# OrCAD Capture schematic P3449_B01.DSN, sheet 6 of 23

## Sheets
6 0017_DisplayPort: size Custom
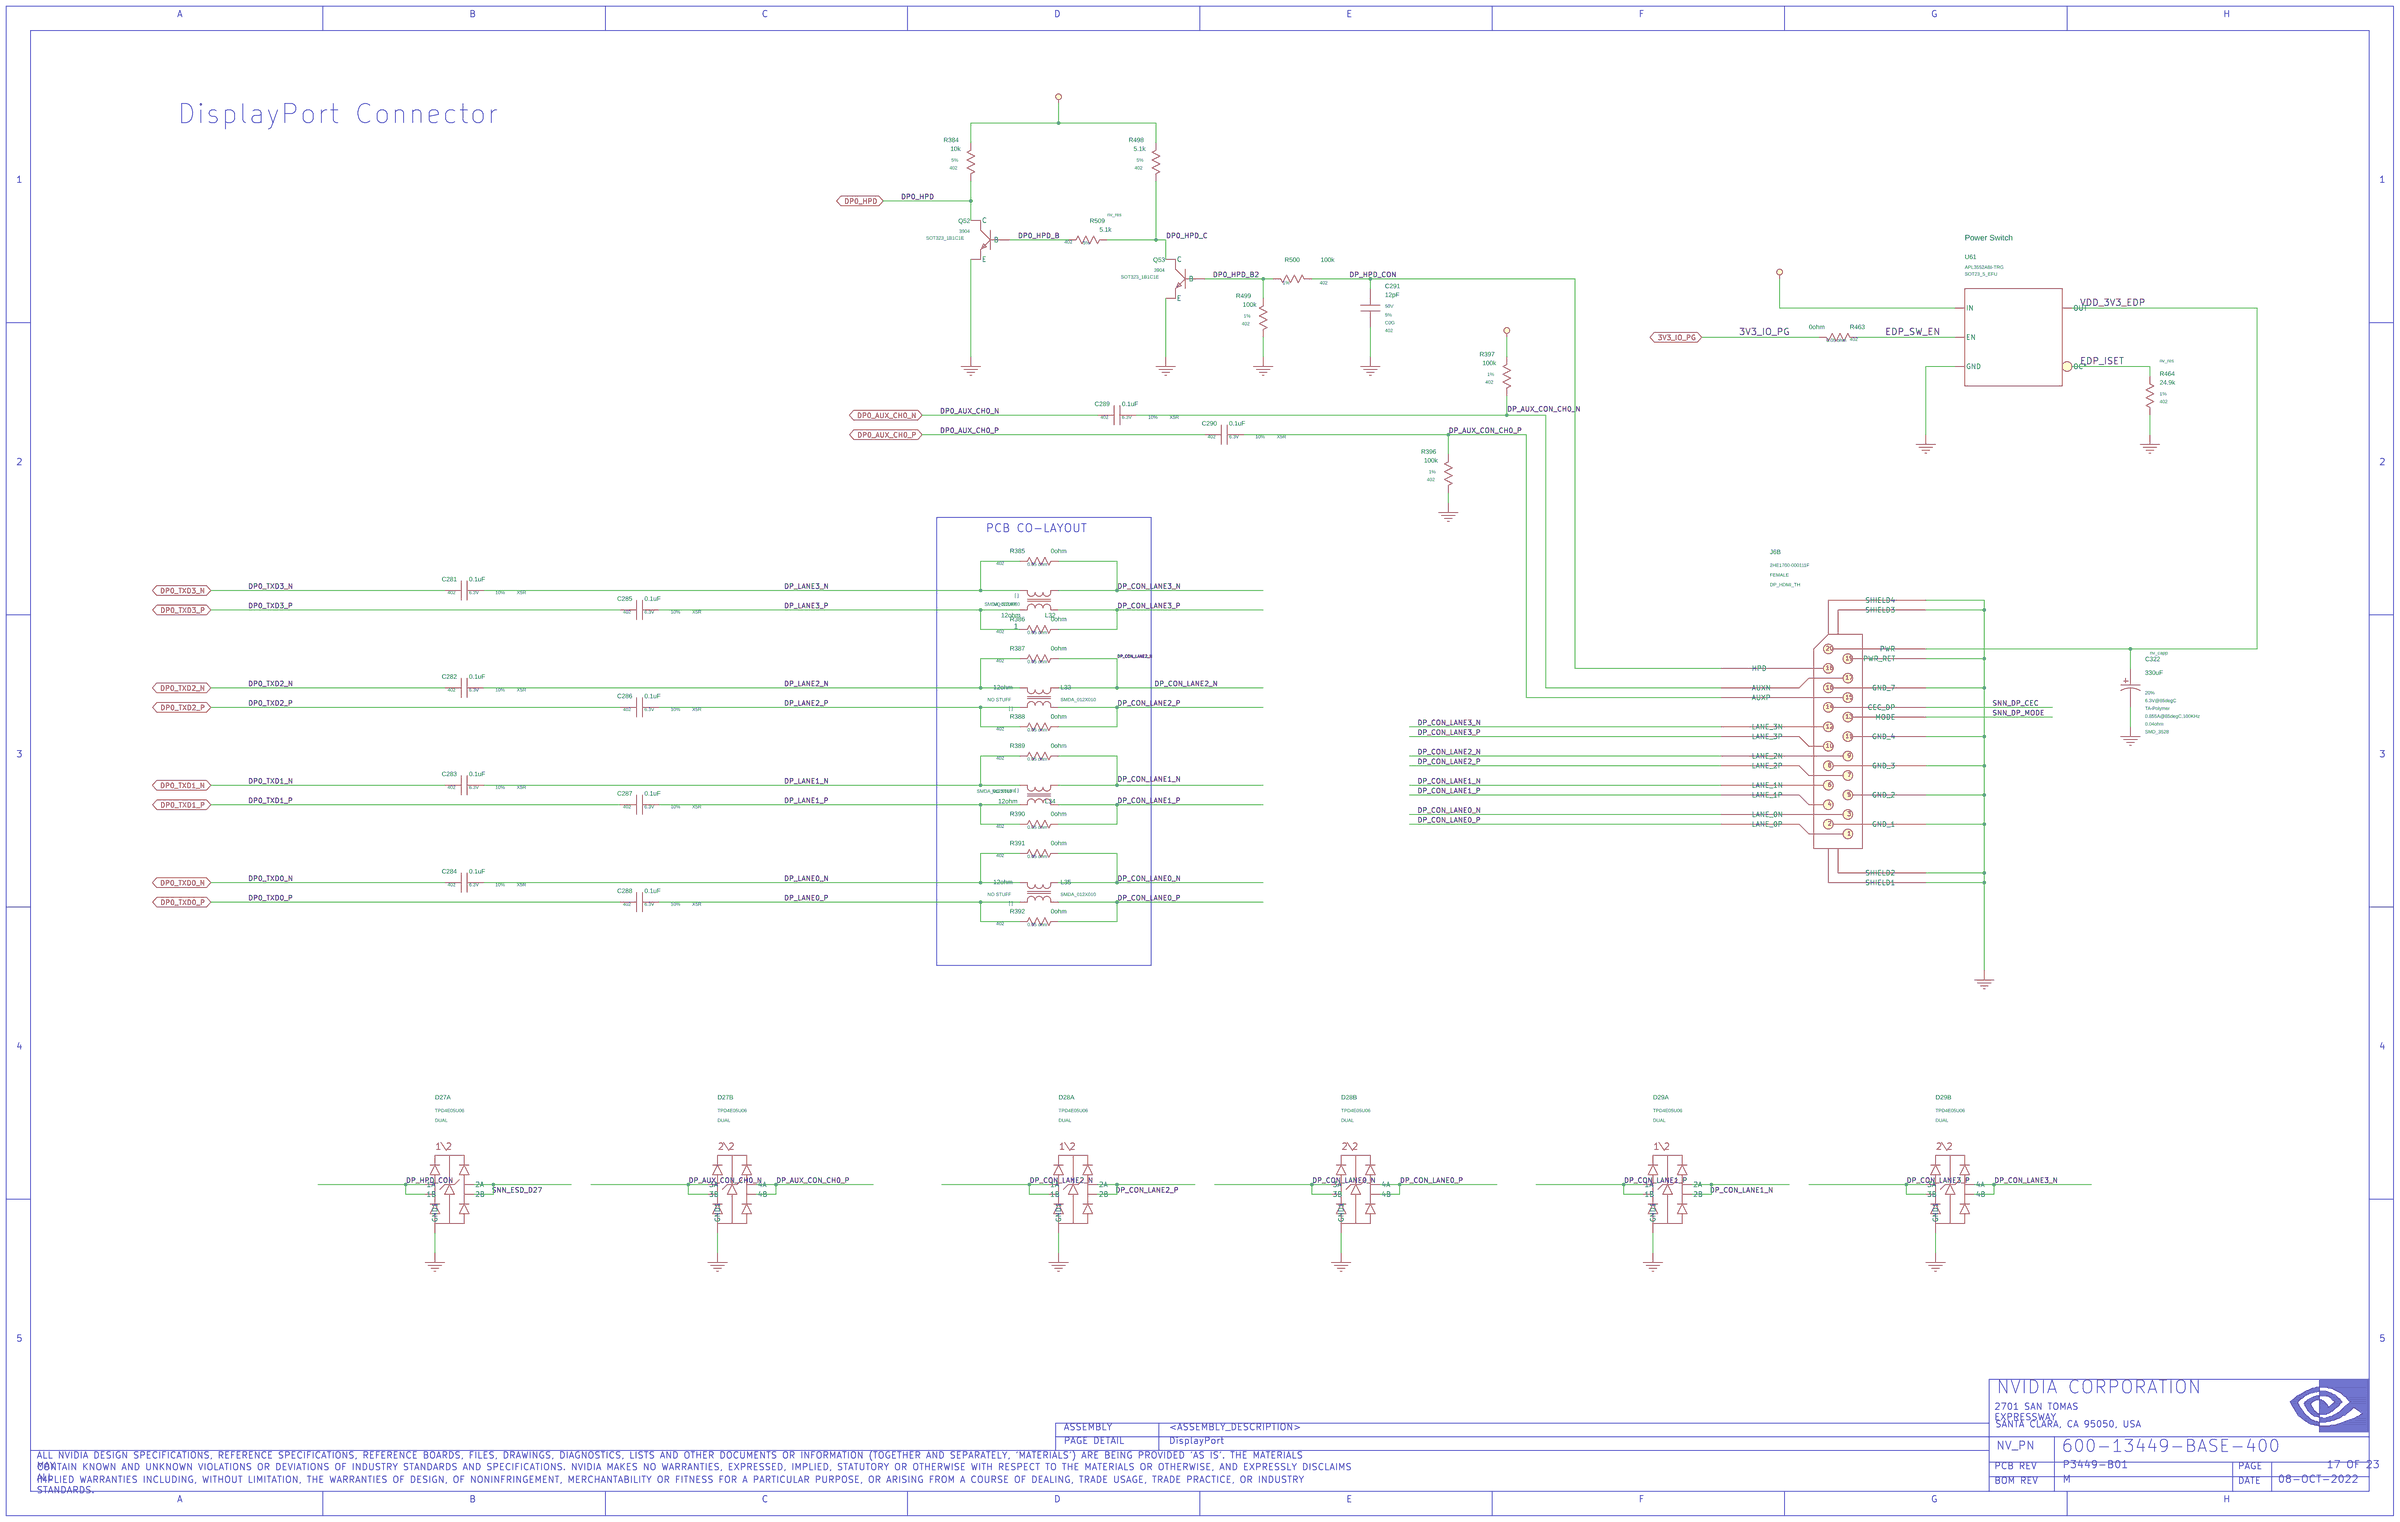
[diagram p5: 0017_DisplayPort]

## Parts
C281  0.1uF  [402]
C282  0.1uF  [402]
C283  0.1uF  [402]
C284  0.1uF  [402]
C285  0.1uF  [402]
C286  0.1uF  [402]
C287  0.1uF  [402]
C288  0.1uF  [402]
C289  0.1uF  [402]
C290  0.1uF  [402]
C291  12pF  [402]
C322  330uF  [CAP_SMD_3528]
D27  D_ESD_DIFFPAIR  [TSLP10_P050_025X010]  (sections A,B)
D28  D_ESD_DIFFPAIR  [TSLP10_P050_025X010]  (sections A,B)
D29  D_ESD_DIFFPAIR  [TSLP10_P050_025X010]  (sections A,B)
J6  CON_HDMI_DISPLAYPORT  [CON_HDMI_019_DP_020_TH_RA_F_181X180_B]  (sections A,B)
L32  12ohm  [IND_NONRKO_SMD_012X010]
L33  12ohm  [IND_NONRKO_SMD_012X010]
L34  12ohm  [IND_NONRKO_SMD_012X010]
L35  12ohm  [IND_NONRKO_SMD_012X010]
Q52  Q_NPN  [SOT323_D]
Q53  Q_NPN  [SOT323_D]
R384  10k  [402]
R385  0ohm  [402]
R386  0ohm  [402]
R387  0ohm  [402]
R388  0ohm  [402]
R389  0ohm  [402]
R390  0ohm  [402]
R391  0ohm  [402]
R392  0ohm  [402]
R396  100k  [402]
R397  100k  [402]
R463  0ohm  [402]
R464  24.9k  [402]
R498  5.1k  [402]
R499  100k  [402]
R500  100k  [402]
R509  5.1k  [402]
U61  U_PWR_SW_UL  [SOT23_5]

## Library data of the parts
C281 = C: ASSEMBLY: EDP; CDS_LIB: discrete; CDS_PART_NAME: C_0402-0.1UF,X5R,10%,6.3V,039-0007-000; CDS_PHYS_PART_NAME: C_0402-0.1UF,X5R,10%,6.3V,039-0007-000-0.1UF,039-0007-000; CDS_SEC: 1; DEVICE_TYPENAME: C_0402-01UFX5R1063V039-0007-000-01UF039-0007-000; DRAWING: @P3449_B01_LIB.P3449_B01(SCH_1):PAGE17; MAT: X5R; MAX_VOLTAGE: 6.3V; NO_XNET: 1; NV_PN: 039-0007-000; PATH: I22; PHYS_PAGE: 17; ROT: 0; SEC: 1; SIGNAL_MODEL: nv_cap; TOL: 10%; VER: 2; XY: (-9800,4600)
C282 = C: ASSEMBLY: EDP; CDS_LIB: discrete; CDS_PART_NAME: C_0402-0.1UF,X5R,10%,6.3V,039-0007-000; CDS_PHYS_PART_NAME: C_0402-0.1UF,X5R,10%,6.3V,039-0007-000-0.1UF,039-0007-000; CDS_SEC: 1; DEVICE_TYPENAME: C_0402-01UFX5R1063V039-0007-000-01UF039-0007-000; DRAWING: @P3449_B01_LIB.P3449_B01(SCH_1):PAGE17; MAT: X5R; MAX_VOLTAGE: 6.3V; NO_XNET: 1; NV_PN: 039-0007-000; PATH: I28; PHYS_PAGE: 17; ROT: 0; SEC: 1; SIGNAL_MODEL: nv_cap; TOL: 10%; VER: 2; XY: (-9800,4100)
C283 = C: ASSEMBLY: EDP; CDS_LIB: discrete; CDS_PART_NAME: C_0402-0.1UF,X5R,10%,6.3V,039-0007-000; CDS_PHYS_PART_NAME: C_0402-0.1UF,X5R,10%,6.3V,039-0007-000-0.1UF,039-0007-000; CDS_SEC: 1; DEVICE_TYPENAME: C_0402-01UFX5R1063V039-0007-000-01UF039-0007-000; DRAWING: @P3449_B01_LIB.P3449_B01(SCH_1):PAGE17; MAT: X5R; MAX_VOLTAGE: 6.3V; NO_XNET: 1; NV_PN: 039-0007-000; PATH: I29; PHYS_PAGE: 17; ROT: 0; SEC: 1; SIGNAL_MODEL: nv_cap; TOL: 10%; VER: 2; XY: (-9800,3600)
C284 = C: ASSEMBLY: EDP; CDS_LIB: discrete; CDS_PART_NAME: C_0402-0.1UF,X5R,10%,6.3V,039-0007-000; CDS_PHYS_PART_NAME: C_0402-0.1UF,X5R,10%,6.3V,039-0007-000-0.1UF,039-0007-000; CDS_SEC: 1; DEVICE_TYPENAME: C_0402-01UFX5R1063V039-0007-000-01UF039-0007-000; DRAWING: @P3449_B01_LIB.P3449_B01(SCH_1):PAGE17; MAT: X5R; MAX_VOLTAGE: 6.3V; NO_XNET: 1; NV_PN: 039-0007-000; PATH: I27; PHYS_PAGE: 17; ROT: 0; SEC: 1; SIGNAL_MODEL: nv_cap; TOL: 10%; VER: 2; XY: (-9800,3100)
C285 = C: ASSEMBLY: EDP; CDS_LIB: discrete; CDS_PART_NAME: C_0402-0.1UF,X5R,10%,6.3V,039-0007-000; CDS_PHYS_PART_NAME: C_0402-0.1UF,X5R,10%,6.3V,039-0007-000-0.1UF,039-0007-000; CDS_SEC: 1; DEVICE_TYPENAME: C_0402-01UFX5R1063V039-0007-000-01UF039-0007-000; DRAWING: @P3449_B01_LIB.P3449_B01(SCH_1):PAGE17; MAT: X5R; MAX_VOLTAGE: 6.3V; NO_XNET: 1; NV_PN: 039-0007-000; PATH: I23; PHYS_PAGE: 17; ROT: 0; SEC: 1; SIGNAL_MODEL: nv_cap; TOL: 10%; VER: 2; XY: (-8900,4500)
C286 = C: ASSEMBLY: EDP; CDS_LIB: discrete; CDS_PART_NAME: C_0402-0.1UF,X5R,10%,6.3V,039-0007-000; CDS_PHYS_PART_NAME: C_0402-0.1UF,X5R,10%,6.3V,039-0007-000-0.1UF,039-0007-000; CDS_SEC: 1; DEVICE_TYPENAME: C_0402-01UFX5R1063V039-0007-000-01UF039-0007-000; DRAWING: @P3449_B01_LIB.P3449_B01(SCH_1):PAGE17; MAT: X5R; MAX_VOLTAGE: 6.3V; NO_XNET: 1; NV_PN: 039-0007-000; PATH: I24; PHYS_PAGE: 17; ROT: 0; SEC: 1; SIGNAL_MODEL: nv_cap; TOL: 10%; VER: 2; XY: (-8900,4000)
C287 = C: ASSEMBLY: EDP; CDS_LIB: discrete; CDS_PART_NAME: C_0402-0.1UF,X5R,10%,6.3V,039-0007-000; CDS_PHYS_PART_NAME: C_0402-0.1UF,X5R,10%,6.3V,039-0007-000-0.1UF,039-0007-000; CDS_SEC: 1; DEVICE_TYPENAME: C_0402-01UFX5R1063V039-0007-000-01UF039-0007-000; DRAWING: @P3449_B01_LIB.P3449_B01(SCH_1):PAGE17; MAT: X5R; MAX_VOLTAGE: 6.3V; NO_XNET: 1; NV_PN: 039-0007-000; PATH: I25; PHYS_PAGE: 17; ROT: 0; SEC: 1; SIGNAL_MODEL: nv_cap; TOL: 10%; VER: 2; XY: (-8900,3500)
C288 = C: ASSEMBLY: EDP; CDS_LIB: discrete; CDS_PART_NAME: C_0402-0.1UF,X5R,10%,6.3V,039-0007-000; CDS_PHYS_PART_NAME: C_0402-0.1UF,X5R,10%,6.3V,039-0007-000-0.1UF,039-0007-000; CDS_SEC: 1; DEVICE_TYPENAME: C_0402-01UFX5R1063V039-0007-000-01UF039-0007-000; DRAWING: @P3449_B01_LIB.P3449_B01(SCH_1):PAGE17; MAT: X5R; MAX_VOLTAGE: 6.3V; NO_XNET: 1; NV_PN: 039-0007-000; PATH: I26; PHYS_PAGE: 17; ROT: 0; SEC: 1; SIGNAL_MODEL: nv_cap; TOL: 10%; VER: 2; XY: (-8900,3000)
C289 = C: ASSEMBLY: EDP; CDS_LIB: discrete; CDS_PART_NAME: C_0402-0.1UF,X5R,10%,6.3V,039-0007-000; CDS_PHYS_PART_NAME: C_0402-0.1UF,X5R,10%,6.3V,039-0007-000-0.1UF,039-0007-000; CDS_SEC: 1; DEVICE_TYPENAME: C_0402-01UFX5R1063V039-0007-000-01UF039-0007-000; DRAWING: @P3449_B01_LIB.P3449_B01(SCH_1):PAGE17; MAT: X5R; MAX_VOLTAGE: 6.3V; NV_PN: 039-0007-000; PATH: I38; PHYS_PAGE: 17; ROT: 0; SEC: 1; SIGNAL_MODEL: nv_cap; TOL: 10%; VER: 2; XY: (-6450,5500)
C290 = C: ASSEMBLY: EDP; CDS_LIB: discrete; CDS_PART_NAME: C_0402-0.1UF,X5R,10%,6.3V,039-0007-000; CDS_PHYS_PART_NAME: C_0402-0.1UF,X5R,10%,6.3V,039-0007-000-0.1UF,039-0007-000; CDS_SEC: 1; DEVICE_TYPENAME: C_0402-01UFX5R1063V039-0007-000-01UF039-0007-000; DRAWING: @P3449_B01_LIB.P3449_B01(SCH_1):PAGE17; MAT: X5R; MAX_VOLTAGE: 6.3V; NV_PN: 039-0007-000; PATH: I39; PHYS_PAGE: 17; ROT: 0; SEC: 1; SIGNAL_MODEL: nv_cap; TOL: 10%; VER: 2; XY: (-5900,5400)
C291 = C#1: ASSEMBLY: EDP; CDS_LIB: discrete; CDS_PART_NAME: C_0402-12PF,C0G,5%,50V,035-0014-000; CDS_PHYS_PART_NAME: C_0402-12PF,C0G,5%,50V,035-0014-000-035-0014-000,12PF; CDS_SEC: 1; CHIPS_PART_NAME: C; DEVICE_TYPENAME: C_0402-12PFC0G550V035-0014-000-035-0014-00012PF; DRAWING: @P3449_B01_LIB.P3449_B01(SCH_1):PAGE17; ESL: N/A; ESR: N/A; MAT: C0G; MAX_VOLTAGE: 50V; NV_PN: 035-0014-000; PATH: I45; PHYS_PAGE: 17; ROT: 0; SEC: 1; SIGNAL_MODEL: nv_cap; TOL: 5%; VER: 1; XY: (-5150,6050)
C322 = C_POL: ASSEMBLY: EDP; CDS_LIB: discrete; CDS_PART_NAME: C_POL_SMD_3528-330UF,TA-POLYMER,20%,6.3V@85DEGC,0.04OHM,9.999UH,0.855A@85DEGC,100KHZ,032-0696-000; CDS_PHYS_PART_NAME: C_POL_SMD_3528-330UF,TA-POLYMER,20%,6.3V@85DEGC,0.04OHM,9.999UH,0.855A@85DEGC,100KHZ,032-0696-000-032-0696-000,330UF; CDS_SEC: 1; DEVICE_TYPENAME: C_POL_SMD_3528-330UFTA-POLYMER2063V85DEGC004OHM9999UH0855A85DEGC100KHZ032-0696-000-032-0696-000330UF; DRAWING: @P3449_B01_LIB.P3449_B01(SCH_1):PAGE17; ESL: 9.999uH; ESR: 0.04ohm; MAT: TA-Polymer; MAX_VOLTAGE: 6.3V@85degC; NV_PN: 032-0696-000; PACK_TYPE: SMD_3528; PATH: I89; PHYS_PAGE: 17; RIPPLE_CURRENT: 0.855A@85degC,100KHz; ROT: 0; SEC: 1; SIGNAL_MODEL: nv_capp; TOL: 20%; VER: 1; XY: (-1250,4100)
D27 = D_ESD_DIFFPAIR: ASSEMBLY: EDP; BREAKDOWN_VOLTAGE_MIN_TYP: 6V; CAPACITANCE_MAX_TYP: 0.5pF; CDS_LIB: discrete; CDS_PART_NAME: D_ESD_DIFFPAIR_DUAL-TPD4E05U06,2 DIFFPAIR,UNI-DIRECTIONAL,5.5V,10UA,6V,10V@1A,0.5PF,090-0231-000; CDS_PHYS_PART_NAME: D_ESD_DIFFPAIR_DUAL-TPD4E05U06,2 DIFFPAIR,UNI-DIRECTIONAL,5.5V,10UA,6V,10V@1A,0.5PF,090-0231-000-090-0231-000; CDS_SEC: 1; CLAMPING_VOLTAGE: 10V@1A; CONFIGURATION: 2 Diffpair; CaptureCellPackProp: D_ESD_DIFFPAIRA; DEVICE_TYPENAME: D_ESD_DIFFPAIR_DUAL-TPD4E05U062DIFFPAIRUNI-DIRECTIONAL55V10UA6V10V1A05PF090-0231-000-090-0231-000; DRAWING: @P3449_B01_LIB.P3449_B01(SCH_1):PAGE17; MAX_REVERSE_LEAKAGE_CURRENT: 10uA; MAX_REVERSE_VOLTAGE: 5.5V; NV_NAME: TPD4E05U06; NV_PN: 090-0231-000; PACK_TYPE: DUAL; PATH: I64; PHYS_PAGE: 17; POLARITY: Uni-Directional; ROT: 0; SEC: 1; VER: 1; XY: (-9900,1550)
D28 = D_ESD_DIFFPAIR: ASSEMBLY: EDP; BREAKDOWN_VOLTAGE_MIN_TYP: 6V; CAPACITANCE_MAX_TYP: 0.5pF; CDS_LIB: discrete; CDS_PART_NAME: D_ESD_DIFFPAIR_DUAL-TPD4E05U06,2 DIFFPAIR,UNI-DIRECTIONAL,5.5V,10UA,6V,10V@1A,0.5PF,090-0231-000; CDS_PHYS_PART_NAME: D_ESD_DIFFPAIR_DUAL-TPD4E05U06,2 DIFFPAIR,UNI-DIRECTIONAL,5.5V,10UA,6V,10V@1A,0.5PF,090-0231-000-090-0231-000; CDS_SEC: 1; CLAMPING_VOLTAGE: 10V@1A; CONFIGURATION: 2 Diffpair; CaptureCellPackProp: D_ESD_DIFFPAIRA; DEVICE_TYPENAME: D_ESD_DIFFPAIR_DUAL-TPD4E05U062DIFFPAIRUNI-DIRECTIONAL55V10UA6V10V1A05PF090-0231-000-090-0231-000; DRAWING: @P3449_B01_LIB.P3449_B01(SCH_1):PAGE17; MAX_REVERSE_LEAKAGE_CURRENT: 10uA; MAX_REVERSE_VOLTAGE: 5.5V; NV_NAME: TPD4E05U06; NV_PN: 090-0231-000; PACK_TYPE: DUAL; PATH: I70; PHYS_PAGE: 17; POLARITY: Uni-Directional; ROT: 0; SEC: 1; VER: 1; XY: (-6700,1550)
D29 = D_ESD_DIFFPAIR: ASSEMBLY: EDP; BREAKDOWN_VOLTAGE_MIN_TYP: 6V; CAPACITANCE_MAX_TYP: 0.5pF; CDS_LIB: discrete; CDS_PART_NAME: D_ESD_DIFFPAIR_DUAL-TPD4E05U06,2 DIFFPAIR,UNI-DIRECTIONAL,5.5V,10UA,6V,10V@1A,0.5PF,090-0231-000; CDS_PHYS_PART_NAME: D_ESD_DIFFPAIR_DUAL-TPD4E05U06,2 DIFFPAIR,UNI-DIRECTIONAL,5.5V,10UA,6V,10V@1A,0.5PF,090-0231-000-090-0231-000; CDS_SEC: 2; CLAMPING_VOLTAGE: 10V@1A; CONFIGURATION: 2 Diffpair; CaptureCellPackProp: D_ESD_DIFFPAIRB; DEVICE_TYPENAME: D_ESD_DIFFPAIR_DUAL-TPD4E05U062DIFFPAIRUNI-DIRECTIONAL55V10UA6V10V1A05PF090-0231-000-090-0231-000; DRAWING: @P3449_B01_LIB.P3449_B01(SCH_1):PAGE17; MAX_REVERSE_LEAKAGE_CURRENT: 10uA; MAX_REVERSE_VOLTAGE: 5.5V; NV_NAME: TPD4E05U06; NV_PN: 090-0231-000; PACK_TYPE: DUAL; PATH: I72; PHYS_PAGE: 17; POLARITY: Uni-Directional; ROT: 0; SEC: 2; VER: 2; XY: (-2200,1550)
J6 = CON_HDMI_DISPLAYPORT: ANGLE: 90; ASSEMBLY: HDMI; CDS_LIB: electro_mechanic; CDS_PART_NAME: CON_HDMI_DISPLAYPORT_DP_HDMI_TH-2HE1700-000111F,FEMALE,1.4MM,90,YES,YES,YES,YES,YES,40 MV,500 MA,064-0374-000; CDS_PHYS_PART_NAME: CON_HDMI_DISPLAYPORT_DP_HDMI_TH-2HE1700-000111F,FEMALE,1.4MM,90,YES,YES,YES,YES,YES,40 MV,500 MA,064-0374-000-064-0374-000; CDS_SEC: 1; CaptureCellPackProp: CON_HDMI_DISPLAYPORTA; DEVICE_TYPENAME: CON_HDMI_DISPLAYPORT_DP_HDMI_TH-2HE1700-000111FFEMALE14MM90YESYESYESYESYES40MV500MA064-0374-000-064-0374-000; DRAWING: @P3449_B01_LIB.P3449_B01(SCH_1):PAGE16; EMI_GROUND_TAB: YES; GENDER: FEMALE; LATCHING: YES; MAX_CURRENT: 500 mA; MAX_VOLTAGE: 40 mV; NV_NAME: 1852139-0N055T-H; NV_PN: 064-0374-000; PACK_TYPE: DP_HDMI_TH; PATH: I389; PHYS_PAGE: 16; PITCH: 1.4mm; REFLOW: YES; ROT: 0; SEC: 1; SHIELDED: YES; SHROUDED: YES; VER: 1; XY: (-600,2950)
L32 = L_CMF_4P#1: ASSEMBLY: EDP; CDS_LIB: discrete; CDS_PART_NAME: L_CMF_4P_SMDA_012X010-12OHM,[ ],25%,0.1A,1.5OHM,MCZ1210DH120L2TA0G,102-0066-000; CDS_PHYS_PART_NAME: L_CMF_4P_SMDA_012X010-12OHM,[ ],25%,0.1A,1.5OHM,MCZ1210DH120L2TA0G,102-0066-000-102-0066-000,12OHM; CDS_SEC: 1; CHIPS_PART_NAME: L_CMF_4P; DC_RESISTANCE: 1.5ohm; DEVICE_TYPENAME: L_CMF_4P_SMDA_012X010-12OHM2501A15OHMMCZ1210DH120L2TA0G102-0066-000-102-0066-00012OHM; DRAWING: @P3449_B01_LIB.P3449_B01(SCH_1):PAGE17; MAT: [ ]; MAX_CURRENT: 0.1A; NO_XNET_CONNECTION: 1; NV_NAME: MCZ1210DH120L2TA0G; NV_PN: 102-0066-000; PACK_TYPE: SMDA_012X010; PATH: I11; PHYS_PAGE: 17; PLACEMENT_NOTE: CoLayout with R563, R565; ROT: 4; SEC: 1; SEC_TYPE: SMDA_012X010; SIGNAL_MODEL: nv_ind_cmf_4p; SKU: NO STUFF; TOL: 25%; VER: 1; XY: (-6850,4550)
L33 = L_CMF_4P#1: ASSEMBLY: EDP; CDS_LIB: discrete; CDS_PART_NAME: L_CMF_4P_SMDA_012X010-12OHM,[ ],25%,0.1A,1.5OHM,MCZ1210DH120L2TA0G,102-0066-000; CDS_PHYS_PART_NAME: L_CMF_4P_SMDA_012X010-12OHM,[ ],25%,0.1A,1.5OHM,MCZ1210DH120L2TA0G,102-0066-000-102-0066-000,12OHM; CDS_SEC: 1; CHIPS_PART_NAME: L_CMF_4P; DC_RESISTANCE: 1.5ohm; DEVICE_TYPENAME: L_CMF_4P_SMDA_012X010-12OHM2501A15OHMMCZ1210DH120L2TA0G102-0066-000-102-0066-00012OHM; DRAWING: @P3449_B01_LIB.P3449_B01(SCH_1):PAGE17; MAT: [ ]; MAX_CURRENT: 0.1A; NV_NAME: MCZ1210DH120L2TA0G; NV_PN: 102-0066-000; PACK_TYPE: SMDA_012X010; PATH: I14; PHYS_PAGE: 17; PLACEMENT_NOTE: CoLayout with R568, R571; ROT: 2; SEC: 1; SEC_TYPE: SMDA_012X010; SIGNAL_MODEL: nv_ind_cmf_4p; SKU: NO STUFF; TOL: 25%; VER: 1; XY: (-6850,4050)
L34 = L_CMF_4P#1: ASSEMBLY: EDP; CDS_LIB: discrete; CDS_PART_NAME: L_CMF_4P_SMDA_012X010-12OHM,[ ],25%,0.1A,1.5OHM,MCZ1210DH120L2TA0G,102-0066-000; CDS_PHYS_PART_NAME: L_CMF_4P_SMDA_012X010-12OHM,[ ],25%,0.1A,1.5OHM,MCZ1210DH120L2TA0G,102-0066-000-102-0066-000,12OHM; CDS_SEC: 1; CHIPS_PART_NAME: L_CMF_4P; DC_RESISTANCE: 1.5ohm; DEVICE_TYPENAME: L_CMF_4P_SMDA_012X010-12OHM2501A15OHMMCZ1210DH120L2TA0G102-0066-000-102-0066-00012OHM; DRAWING: @P3449_B01_LIB.P3449_B01(SCH_1):PAGE17; MAT: [ ]; MAX_CURRENT: 0.1A; NV_NAME: MCZ1210DH120L2TA0G; NV_PN: 102-0066-000; PACK_TYPE: SMDA_012X010; PATH: I17; PHYS_PAGE: 17; PLACEMENT_NOTE: CoLayout with R577, R579; ROT: 4; SEC: 1; SEC_TYPE: SMDA_012X010; SIGNAL_MODEL: nv_ind_cmf_4p; SKU: NO STUFF; TOL: 25%; VER: 1; XY: (-6850,3550)
L35 = L_CMF_4P#1: ASSEMBLY: EDP; CDS_LIB: discrete; CDS_PART_NAME: L_CMF_4P_SMDA_012X010-12OHM,[ ],25%,0.1A,1.5OHM,MCZ1210DH120L2TA0G,102-0066-000; CDS_PHYS_PART_NAME: L_CMF_4P_SMDA_012X010-12OHM,[ ],25%,0.1A,1.5OHM,MCZ1210DH120L2TA0G,102-0066-000-102-0066-000,12OHM; CDS_SEC: 1; CHIPS_PART_NAME: L_CMF_4P; DC_RESISTANCE: 1.5ohm; DEVICE_TYPENAME: L_CMF_4P_SMDA_012X010-12OHM2501A15OHMMCZ1210DH120L2TA0G102-0066-000-102-0066-00012OHM; DRAWING: @P3449_B01_LIB.P3449_B01(SCH_1):PAGE17; MAT: [ ]; MAX_CURRENT: 0.1A; NV_NAME: MCZ1210DH120L2TA0G; NV_PN: 102-0066-000; PACK_TYPE: SMDA_012X010; PATH: I20; PHYS_PAGE: 17; PLACEMENT_NOTE: CoLayout with R583, R584; ROT: 2; SEC: 1; SEC_TYPE: SMDA_012X010; SIGNAL_MODEL: nv_ind_cmf_4p; SKU: NO STUFF; TOL: 25%; VER: 1; XY: (-6850,3050)
Q52 = Q_NPN: ASSEMBLY: SHUTDOWN; CDS_LIB: discrete; CDS_PART_NAME: Q_NPN_SOT323_1B1C1E-3904,40V,0.3V,0.2A,0.2A,6V,0.15W,300-1128-000; CDS_PHYS_PART_NAME: Q_NPN_SOT323_1B1C1E-3904,40V,0.3V,0.2A,0.2A,6V,0.15W,300-1128-000-300-1128-000; CDS_SEC: 1; CONTINUOUS_CURRENT: 0.2A; DEVICE_TYPENAME: Q_NPN_SOT323_1B1C1E-390440V03V02A02A6V015W300-1128-000-300-1128-000; DRAWING: @P3449_B01_LIB.P3449_B01(SCH_1):PAGE17; MAX_CURRENT: 0.2A; MAX_VOLTAGE: 40V; MAX_WATTAGE: 0.15W; NV_NAME: 3904; NV_PN: 300-1128-000; PACK_TYPE: SOT323_1B1C1E; PATH: I90; PHYS_PAGE: 17; ROT: 2; SEC: 1; VER: 1; V_BE_GS: 6V; V_CE_SAT: 0.3V; XY: (-7100,6400)
Q53 = Q_NPN: ASSEMBLY: SHUTDOWN; CDS_LIB: discrete; CDS_PART_NAME: Q_NPN_SOT323_1B1C1E-3904,40V,0.3V,0.2A,0.2A,6V,0.15W,300-1128-000; CDS_PHYS_PART_NAME: Q_NPN_SOT323_1B1C1E-3904,40V,0.3V,0.2A,0.2A,6V,0.15W,300-1128-000-300-1128-000; CDS_SEC: 1; CONTINUOUS_CURRENT: 0.2A; DEVICE_TYPENAME: Q_NPN_SOT323_1B1C1E-390440V03V02A02A6V015W300-1128-000-300-1128-000; DRAWING: @P3449_B01_LIB.P3449_B01(SCH_1):PAGE17; MAX_CURRENT: 0.2A; MAX_VOLTAGE: 40V; MAX_WATTAGE: 0.15W; NV_NAME: 3904; NV_PN: 300-1128-000; PACK_TYPE: SOT323_1B1C1E; PATH: I91; PHYS_PAGE: 17; ROT: 2; SEC: 1; VER: 1; V_BE_GS: 6V; V_CE_SAT: 0.3V; XY: (-6100,6200)
R384 = R: ASSEMBLY: EDP; CDS_LIB: discrete; CDS_PART_NAME: R_0402-10K,5 %,62.5MW,195-0486-000; CDS_PHYS_PART_NAME: R_0402-10K,5 %,62.5MW,195-0486-000-10K,195-0486-000; CDS_SEC: 1; DEVICE_TYPENAME: R_0402-10K5625MW195-0486-000-10K195-0486-000; DRAWING: @P3449_B01_LIB.P3449_B01(SCH_1):PAGE17; MAX_WATTAGE: 62.5mW; NV_PN: 195-0486-000; PATH: I50; PHYS_PAGE: 17; ROT: 2; SEC: 1; SIGNAL_MODEL: nv_res; TOL: 5%; VER: 2; XY: (-7200,6800)
R385 = R#1: ASSEMBLY: EDP; CDS_LIB: discrete; CDS_PART_NAME: R_0402-0OHM,0.05 OHM,62.5MW,195-2655-000; CDS_PHYS_PART_NAME: R_0402-0OHM,0.05 OHM,62.5MW,195-2655-000-0OHM,195-2655-000; CDS_SEC: 1; CHIPS_PART_NAME: R; DEVICE_TYPENAME: R_0402-0OHM005OHM625MW195-2655-000-0OHM195-2655-000; DRAWING: @P3449_B01_LIB.P3449_B01(SCH_1):PAGE17; MAX_WATTAGE: 62.5mW; NV_PN: 195-2655-000; PATH: I7; PHYS_PAGE: 17; PLACEMENT_NOTE: CoLayout with L501; ROT: 0; SEC: 1; SIGNAL_MODEL: nv_res; TOL: 0.05 ohm; VER: 1; XY: (-6850,4750)
R386 = R#1: ASSEMBLY: EDP; CDS_LIB: discrete; CDS_PART_NAME: R_0402-0OHM,0.05 OHM,62.5MW,195-2655-000; CDS_PHYS_PART_NAME: R_0402-0OHM,0.05 OHM,62.5MW,195-2655-000-0OHM,195-2655-000; CDS_SEC: 1; CHIPS_PART_NAME: R; DEVICE_TYPENAME: R_0402-0OHM005OHM625MW195-2655-000-0OHM195-2655-000; DRAWING: @P3449_B01_LIB.P3449_B01(SCH_1):PAGE17; MAX_WATTAGE: 62.5mW; NV_PN: 195-2655-000; PATH: I12; PHYS_PAGE: 17; PLACEMENT_NOTE: CoLayout with L501; ROT: 0; SEC: 1; SIGNAL_MODEL: nv_res; TOL: 0.05 ohm; VER: 1; XY: (-6850,4400)
R387 = R#1: ASSEMBLY: EDP; CDS_LIB: discrete; CDS_PART_NAME: R_0402-0OHM,0.05 OHM,62.5MW,195-2655-000; CDS_PHYS_PART_NAME: R_0402-0OHM,0.05 OHM,62.5MW,195-2655-000-0OHM,195-2655-000; CDS_SEC: 1; CHIPS_PART_NAME: R; DEVICE_TYPENAME: R_0402-0OHM005OHM625MW195-2655-000-0OHM195-2655-000; DRAWING: @P3449_B01_LIB.P3449_B01(SCH_1):PAGE17; MAX_WATTAGE: 62.5mW; NV_PN: 195-2655-000; PATH: I13; PHYS_PAGE: 17; PLACEMENT_NOTE: CoLayout with L503; ROT: 0; SEC: 1; SIGNAL_MODEL: nv_res; TOL: 0.05 ohm; VER: 1; XY: (-6850,4250)
R388 = R#1: ASSEMBLY: EDP; CDS_LIB: discrete; CDS_PART_NAME: R_0402-0OHM,0.05 OHM,62.5MW,195-2655-000; CDS_PHYS_PART_NAME: R_0402-0OHM,0.05 OHM,62.5MW,195-2655-000-0OHM,195-2655-000; CDS_SEC: 1; CHIPS_PART_NAME: R; DEVICE_TYPENAME: R_0402-0OHM005OHM625MW195-2655-000-0OHM195-2655-000; DRAWING: @P3449_B01_LIB.P3449_B01(SCH_1):PAGE17; MAX_WATTAGE: 62.5mW; NV_PN: 195-2655-000; PATH: I15; PHYS_PAGE: 17; PLACEMENT_NOTE: CoLayout with L503; ROT: 0; SEC: 1; SIGNAL_MODEL: nv_res; TOL: 0.05 ohm; VER: 1; XY: (-6850,3900)
R389 = R#1: ASSEMBLY: EDP; CDS_LIB: discrete; CDS_PART_NAME: R_0402-0OHM,0.05 OHM,62.5MW,195-2655-000; CDS_PHYS_PART_NAME: R_0402-0OHM,0.05 OHM,62.5MW,195-2655-000-0OHM,195-2655-000; CDS_SEC: 1; CHIPS_PART_NAME: R; DEVICE_TYPENAME: R_0402-0OHM005OHM625MW195-2655-000-0OHM195-2655-000; DRAWING: @P3449_B01_LIB.P3449_B01(SCH_1):PAGE17; MAX_WATTAGE: 62.5mW; NV_PN: 195-2655-000; PATH: I16; PHYS_PAGE: 17; PLACEMENT_NOTE: CoLayout with L504; ROT: 0; SEC: 1; SIGNAL_MODEL: nv_res; TOL: 0.05 ohm; VER: 1; XY: (-6850,3750)
R390 = R#1: ASSEMBLY: EDP; CDS_LIB: discrete; CDS_PART_NAME: R_0402-0OHM,0.05 OHM,62.5MW,195-2655-000; CDS_PHYS_PART_NAME: R_0402-0OHM,0.05 OHM,62.5MW,195-2655-000-0OHM,195-2655-000; CDS_SEC: 1; CHIPS_PART_NAME: R; DEVICE_TYPENAME: R_0402-0OHM005OHM625MW195-2655-000-0OHM195-2655-000; DRAWING: @P3449_B01_LIB.P3449_B01(SCH_1):PAGE17; MAX_WATTAGE: 62.5mW; NV_PN: 195-2655-000; PATH: I18; PHYS_PAGE: 17; PLACEMENT_NOTE: CoLayout with L504; ROT: 0; SEC: 1; SIGNAL_MODEL: nv_res; TOL: 0.05 ohm; VER: 1; XY: (-6850,3400)
R391 = R#1: ASSEMBLY: EDP; CDS_LIB: discrete; CDS_PART_NAME: R_0402-0OHM,0.05 OHM,62.5MW,195-2655-000; CDS_PHYS_PART_NAME: R_0402-0OHM,0.05 OHM,62.5MW,195-2655-000-0OHM,195-2655-000; CDS_SEC: 1; CHIPS_PART_NAME: R; DEVICE_TYPENAME: R_0402-0OHM005OHM625MW195-2655-000-0OHM195-2655-000; DRAWING: @P3449_B01_LIB.P3449_B01(SCH_1):PAGE17; MAX_WATTAGE: 62.5mW; NV_PN: 195-2655-000; PATH: I19; PHYS_PAGE: 17; PLACEMENT_NOTE: CoLayout with L506; ROT: 0; SEC: 1; SIGNAL_MODEL: nv_res; TOL: 0.05 ohm; VER: 1; XY: (-6850,3250)
R392 = R#1: ASSEMBLY: EDP; CDS_LIB: discrete; CDS_PART_NAME: R_0402-0OHM,0.05 OHM,62.5MW,195-2655-000; CDS_PHYS_PART_NAME: R_0402-0OHM,0.05 OHM,62.5MW,195-2655-000-0OHM,195-2655-000; CDS_SEC: 1; CHIPS_PART_NAME: R; DEVICE_TYPENAME: R_0402-0OHM005OHM625MW195-2655-000-0OHM195-2655-000; DRAWING: @P3449_B01_LIB.P3449_B01(SCH_1):PAGE17; MAX_WATTAGE: 62.5mW; NV_PN: 195-2655-000; PATH: I21; PHYS_PAGE: 17; PLACEMENT_NOTE: CoLayout with L506; ROT: 0; SEC: 1; SIGNAL_MODEL: nv_res; TOL: 0.05 ohm; VER: 1; XY: (-6850,2900)
R396 = R: ASSEMBLY: EDP; CDS_LIB: discrete; CDS_PART_NAME: R_0402-100K,1 %,62.5MW,195-0005-000; CDS_PHYS_PART_NAME: R_0402-100K,1 %,62.5MW,195-0005-000-100K,195-0005-000; CDS_SEC: 1; DEVICE_TYPENAME: R_0402-100K1625MW195-0005-000-100K195-0005-000; DRAWING: @P3449_B01_LIB.P3449_B01(SCH_1):PAGE17; MAX_WATTAGE: 62.5mW; NV_PN: 195-0005-000; PATH: I57; PHYS_PAGE: 17; ROT: 2; SEC: 1; SIGNAL_MODEL: nv_res; TOL: 1%; VER: 2; XY: (-4750,5200)
R397 = R: ASSEMBLY: EDP; CDS_LIB: discrete; CDS_PART_NAME: R_0402-100K,1 %,62.5MW,195-0005-000; CDS_PHYS_PART_NAME: R_0402-100K,1 %,62.5MW,195-0005-000-100K,195-0005-000; CDS_SEC: 1; DEVICE_TYPENAME: R_0402-100K1625MW195-0005-000-100K195-0005-000; DRAWING: @P3449_B01_LIB.P3449_B01(SCH_1):PAGE17; MAX_WATTAGE: 62.5mW; NV_PN: 195-0005-000; PATH: I58; PHYS_PAGE: 17; ROT: 2; SEC: 1; SIGNAL_MODEL: nv_res; TOL: 1%; VER: 2; XY: (-4450,5700)
R463 = R#1: ASSEMBLY: EDP; CDS_LIB: discrete; CDS_PART_NAME: R_0402-0OHM,0.05 OHM,62.5MW,195-2655-000; CDS_PHYS_PART_NAME: R_0402-0OHM,0.05 OHM,62.5MW,195-2655-000-0OHM,195-2655-000; CDS_SEC: 1; CHIPS_PART_NAME: R; DEVICE_TYPENAME: R_0402-0OHM005OHM625MW195-2655-000-0OHM195-2655-000; DRAWING: @P3449_B01_LIB.P3449_B01(SCH_1):PAGE17; MAX_WATTAGE: 62.5mW; NV_PN: 195-2655-000; PATH: I83; PHYS_PAGE: 17; ROT: 2; SEC: 1; SIGNAL_MODEL: nv_res; TOL: 0.05 ohm; VER: 1; XY: (-2750,5900)
R464 = R: ASSEMBLY: EDP; CDS_LIB: discrete; CDS_PART_NAME: R_0402-24.9K,1 %,62.5MW,195-0195-000; CDS_PHYS_PART_NAME: R_0402-24.9K,1 %,62.5MW,195-0195-000-195-0195-000,24.9K; CDS_SEC: 1; DEVICE_TYPENAME: R_0402-249K1625MW195-0195-000-195-0195-000249K; DRAWING: @P3449_B01_LIB.P3449_B01(SCH_1):PAGE17; MAX_WATTAGE: 62.5mW; NV_PN: 195-0195-000; PATH: I84; PHYS_PAGE: 17; ROT: 0; SEC: 1; SIGNAL_MODEL: nv_res; TOL: 1%; VER: 2; XY: (-1150,5600)
R498 = R: ASSEMBLY: EDP; CDS_LIB: discrete; CDS_PART_NAME: R_0402-5.1K,5 %,62.5MW,195-0605-000; CDS_PHYS_PART_NAME: R_0402-5.1K,5 %,62.5MW,195-0605-000-195-0605-000,5.1K; CDS_SEC: 1; DEVICE_TYPENAME: R_0402-51K5625MW195-0605-000-195-0605-00051K; DRAWING: @P3449_B01_LIB.P3449_B01(SCH_1):PAGE17; MAX_WATTAGE: 62.5mW; NV_PN: 195-0605-000; PATH: I93; PHYS_PAGE: 17; ROT: 2; SEC: 1; SIGNAL_MODEL: nv_res; TOL: 5%; VER: 2; XY: (-6250,6800)
R499 = R: ASSEMBLY: EDP; CDS_LIB: discrete; CDS_PART_NAME: R_0402-10K,5 %,62.5MW,195-0486-000; CDS_PHYS_PART_NAME: R_0402-10K,5 %,62.5MW,195-0486-000-10K,195-0486-000; CDS_SEC: 1; DEVICE_TYPENAME: R_0402-10K5625MW195-0486-000-10K195-0486-000; DRAWING: @P3449_B01_LIB.P3449_B01(SCH_1):PAGE17; MAX_WATTAGE: 62.5mW; NV_PN: 195-0486-000; PATH: I95; PHYS_PAGE: 17; ROT: 2; SEC: 1; SIGNAL_MODEL: nv_res; TOL: 1%; VER: 2; XY: (-5700,6000)
R500 = R: ASSEMBLY: EDP; CDS_LIB: discrete; CDS_PART_NAME: R_0402-10K,5 %,62.5MW,195-0486-000; CDS_PHYS_PART_NAME: R_0402-10K,5 %,62.5MW,195-0486-000-10K,195-0486-000; CDS_SEC: 1; DEVICE_TYPENAME: R_0402-10K5625MW195-0486-000-10K195-0486-000; DRAWING: @P3449_B01_LIB.P3449_B01(SCH_1):PAGE17; MAX_WATTAGE: 62.5mW; NV_PN: 195-0486-000; PATH: I94; PHYS_PAGE: 17; ROT: 3; SEC: 1; SIGNAL_MODEL: nv_res; TOL: 1%; VER: 2; XY: (-5550,6200)
R509 = R#1: CDS_LIB: discrete; CDS_PART_NAME: R_0402-5.1K,5 %,62.5MW,195-0605-000; CDS_PHYS_PART_NAME: R_0402-5.1K,5 %,62.5MW,195-0605-000-195-0605-000,5.1K; CDS_SEC: 1; CHIPS_PART_NAME: R; DEVICE_TYPENAME: R_0402-51K5625MW195-0605-000-195-0605-00051K; DRAWING: @P3449_B01_LIB.P3449_B01(SCH_1):PAGE17; MAX_WATTAGE: 62.5mW; NV_PN: 195-0605-000; PATH: I96; PHYS_PAGE: 17; ROT: 0; SEC: 1; SIGNAL_MODEL: nv_res; TOL: 5%; VER: 1; XY: (-6600,6400)
U61 = U_PWR_SW_UL: ASSEMBLY: EDP; CDS_LIB: power_supply; CDS_PART_NAME: U_PWR_SW_UL_SOT23_5_EFU-APL3552ABI-TRG,2.7V..5.5V,2.7V..5.5V,2A,SWITCH,315-1062-000; CDS_PHYS_PART_NAME: U_PWR_SW_UL_SOT23_5_EFU-APL3552ABI-TRG,2.7V..5.5V,2.7V..5.5V,2A,SWITCH,315-1062-000-315-1062-000; CDS_SEC: 1; DEVICE_TYPENAME: U_PWR_SW_UL_SOT23_5_EFU-APL3552ABI-TRG27V55V27V55V2ASWITCH315-1062-000-315-1062-000; DRAWING: @P3449_B01_LIB.P3449_B01(SCH_1):PAGE17; FUNCTION: Power Switch; MAX_CURRENT: 2A; MAX_VOLTAGE: 2.7V..5.5V; NV_NAME: APL3552ABI-TRG; NV_PN: 315-1062-000; OUTPUT_VOLTAGE: 2.7V..5.5V; PACK_TYPE: SOT23_5_EFU; PATH: I80; PHYS_PAGE: 17; ROT: 0; SEC: 1; TYPE: Switch; VER: 1; XY: (-1850,5900)

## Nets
3V3_IO_PG: R463.2 ; also on sheet 11 15
GND: C291.2 C322.2 D27.3(GND1) D28.3(GND1) D29.3(GND1) J6.21(GND_1) J6.24(GND_2) J6.27(GND_3) J6.30(GND_4) J6.35(GND_7) J6.38(PWR_RET) Q52.2(E) Q53.2(E) R396.2 R464.2 R499.2 U61.2(GND) ; also on sheet 1 3 4 5 7 8 9 10 11 12 13 14 15 16 19
VDD_1V8: R384.1 R498.1 ; also on sheet 3 4 7 9 11 19
VDD_3V3_EDP: C322.1 J6.39(PWR) U61.1(OUT)
VDD_3V3_SYS: R397.1 U61.5(IN) ; also on sheet 3 4 5 7 8 9 11 18 19
DP0_AUX_CH0_N: C289.1 ; also on sheet 17
DP0_AUX_CH0_P: C290.1 ; also on sheet 17
DP0_HPD: Q52.3(C) R384.2 ; also on sheet 17
DP0_HPD_B: Q52.1(B) R509.1
DP0_HPD_B2: Q53.1(B) R499.1 R500.1
DP0_HPD_C: Q53.3(C) R498.2 R509.2
DP0_TXD0_N: C284.1 ; also on sheet 17
DP0_TXD0_P: C288.1 ; also on sheet 17
DP0_TXD1_N: C283.1 ; also on sheet 17
DP0_TXD1_P: C287.1 ; also on sheet 17
DP0_TXD2_N: C282.1 ; also on sheet 17
DP0_TXD2_P: C286.1 ; also on sheet 17
DP0_TXD3_N: C281.1 ; also on sheet 17
DP0_TXD3_P: C285.1 ; also on sheet 17
DP_AUX_CON_CH0_N: C289.2 D27.4(3A) D27.7(3B) J6.36(AUXN) R397.2
DP_AUX_CON_CH0_P: C290.2 D27.5(4A) D27.6(4B) J6.34(AUXP) R396.1
DP_CON_LANE0_N: D28.4(3A) D28.7(3B) J6.22(LANE_0N) L35.1 R391.2
DP_CON_LANE0_P: D28.5(4A) D28.6(4B) J6.20(LANE_0P) L35.2 R392.2
DP_CON_LANE1_N: D29.2(2A) D29.9(2B) J6.25(LANE_1N) L34.2 R389.2
DP_CON_LANE1_P: D29.1(1A) D29.10(1B) J6.23(LANE_1P) L34.1 R390.2
DP_CON_LANE2_N: D28.1(1A) D28.10(1B) J6.28(LANE_2N) L33.1 R387.2
DP_CON_LANE2_P: D28.2(2A) D28.9(2B) J6.26(LANE_2P) L33.2 R388.2
DP_CON_LANE3_N: D29.5(4A) D29.6(4B) J6.31(LANE_3N) L32.2 R385.2
DP_CON_LANE3_P: D29.4(3A) D29.7(3B) J6.29(LANE_3P) L32.1 R386.2
DP_HPD_CON: C291.1 D27.1(1A) D27.10(1B) J6.37(HPD) R500.2
DP_LANE0_N: C284.2 L35.4 R391.1
DP_LANE0_P: C288.2 L35.3 R392.1
DP_LANE1_N: C283.2 L34.3 R389.1
DP_LANE1_P: C287.2 L34.4 R390.1
DP_LANE2_N: C282.2 L33.4 R387.1
DP_LANE2_P: C286.2 L33.3 R388.1
DP_LANE3_N: C281.2 L32.3 R385.1
DP_LANE3_P: C285.2 L32.4 R386.1
EDP_ISET: R464.1 U61.3(OC*)
EDP_SW_EN: R463.1 U61.4(EN)
SNN_DP_CEC: J6.33(CEC_DP)
SNN_DP_MODE: J6.32(MODE)
SNN_ESD_D27: D27.2(2A) D27.9(2B)

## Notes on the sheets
sheet 6
- A
- B
- C
- D
- E
- F
- G
- H
- DisplayPort Connector
- 1
- 1
- 2
- 2
- PCB CO-LAYOUT
- 3
- 3
- 4
- 4
- 5
- 5
- NVIDIA CORPORATION
- 2701 SAN TOMAS
  EXPRESSWAY
- ASSEMBLY
- <ASSEMBLY_DESCRIPTION>
- SANTA CLARA, CA 95050, USA
- PAGE DETAIL
- DisplayPort
- NV_PN
- 600-13449-BASE-400
- ALL NVIDIA DESIGN SPECIFICATIONS, REFERENCE SPECIFICATIONS, REFERENCE BOARDS, FILES, DRAWINGS, DIAGNOSTICS, LISTS AND OTHER DOCUMENTS OR INFORMATION (TOGETHER AND SEPARATELY, 'MATERIALS') ARE BEING PROVIDED 'AS IS'. THE MATERIALS
  MAY
- CONTAIN KNOWN AND UNKNOWN VIOLATIONS OR DEVIATIONS OF INDUSTRY STANDARDS AND SPECIFICATIONS. NVIDIA MAKES NO WARRANTIES, EXPRESSED, IMPLIED, STATUTORY OR OTHERWISE WITH RESPECT TO THE MATERIALS OR OTHERWISE, AND EXPRESSLY DISCLAIMS
  ALL
- PCB REV
- P3449-B01
- PAGE
- 17 OF 23
- IMPLIED WARRANTIES INCLUDING, WITHOUT LIMITATION, THE WARRANTIES OF DESIGN, OF NONINFRINGEMENT, MERCHANTABILITY OR FITNESS FOR A PARTICULAR PURPOSE, OR ARISING FROM A COURSE OF DEALING, TRADE USAGE, TRADE PRACTICE, OR INDUSTRY
  STANDARDS.
- BOM REV
- M
- DATE
- 08-OCT-2022
- A
- B
- C
- D
- E
- F
- G
- H
